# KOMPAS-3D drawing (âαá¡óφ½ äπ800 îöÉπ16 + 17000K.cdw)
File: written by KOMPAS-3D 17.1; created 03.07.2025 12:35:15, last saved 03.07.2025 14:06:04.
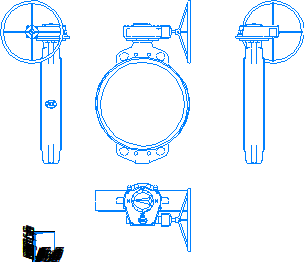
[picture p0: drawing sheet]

Sheet 1: A4, portrait

Title block, sheet 1: sheets: 1; sheet format: A4; stored path: \\adlc.lan\data\АДЛ_ПКД\3D-модели\ADL production\Дисковые поворотные затворы ГРАНВЭЛ\межфланцевый с китайским редуктором Ру16\KOMPAS 2D\Гранвэл Ду800 МФРу16 + 17000K.cdw

Views: Проекционный вид 2, Проекционный вид 3, Проекционный вид 4
Referenced files in \\adlc.lan\data\АДЛ_ПКД\3D-модели\ADL production\Дисковые поворотные затворы ГРАНВЭЛ\межфланцевый с китайским редуктором Ру16\KOMPAS 3D\: Гранвэл Ду800 МФРу16 + 17000K.m3d
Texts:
  Andrey
  АДЛ
Dimensions and other numbers on the sheet: 1:1; 1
